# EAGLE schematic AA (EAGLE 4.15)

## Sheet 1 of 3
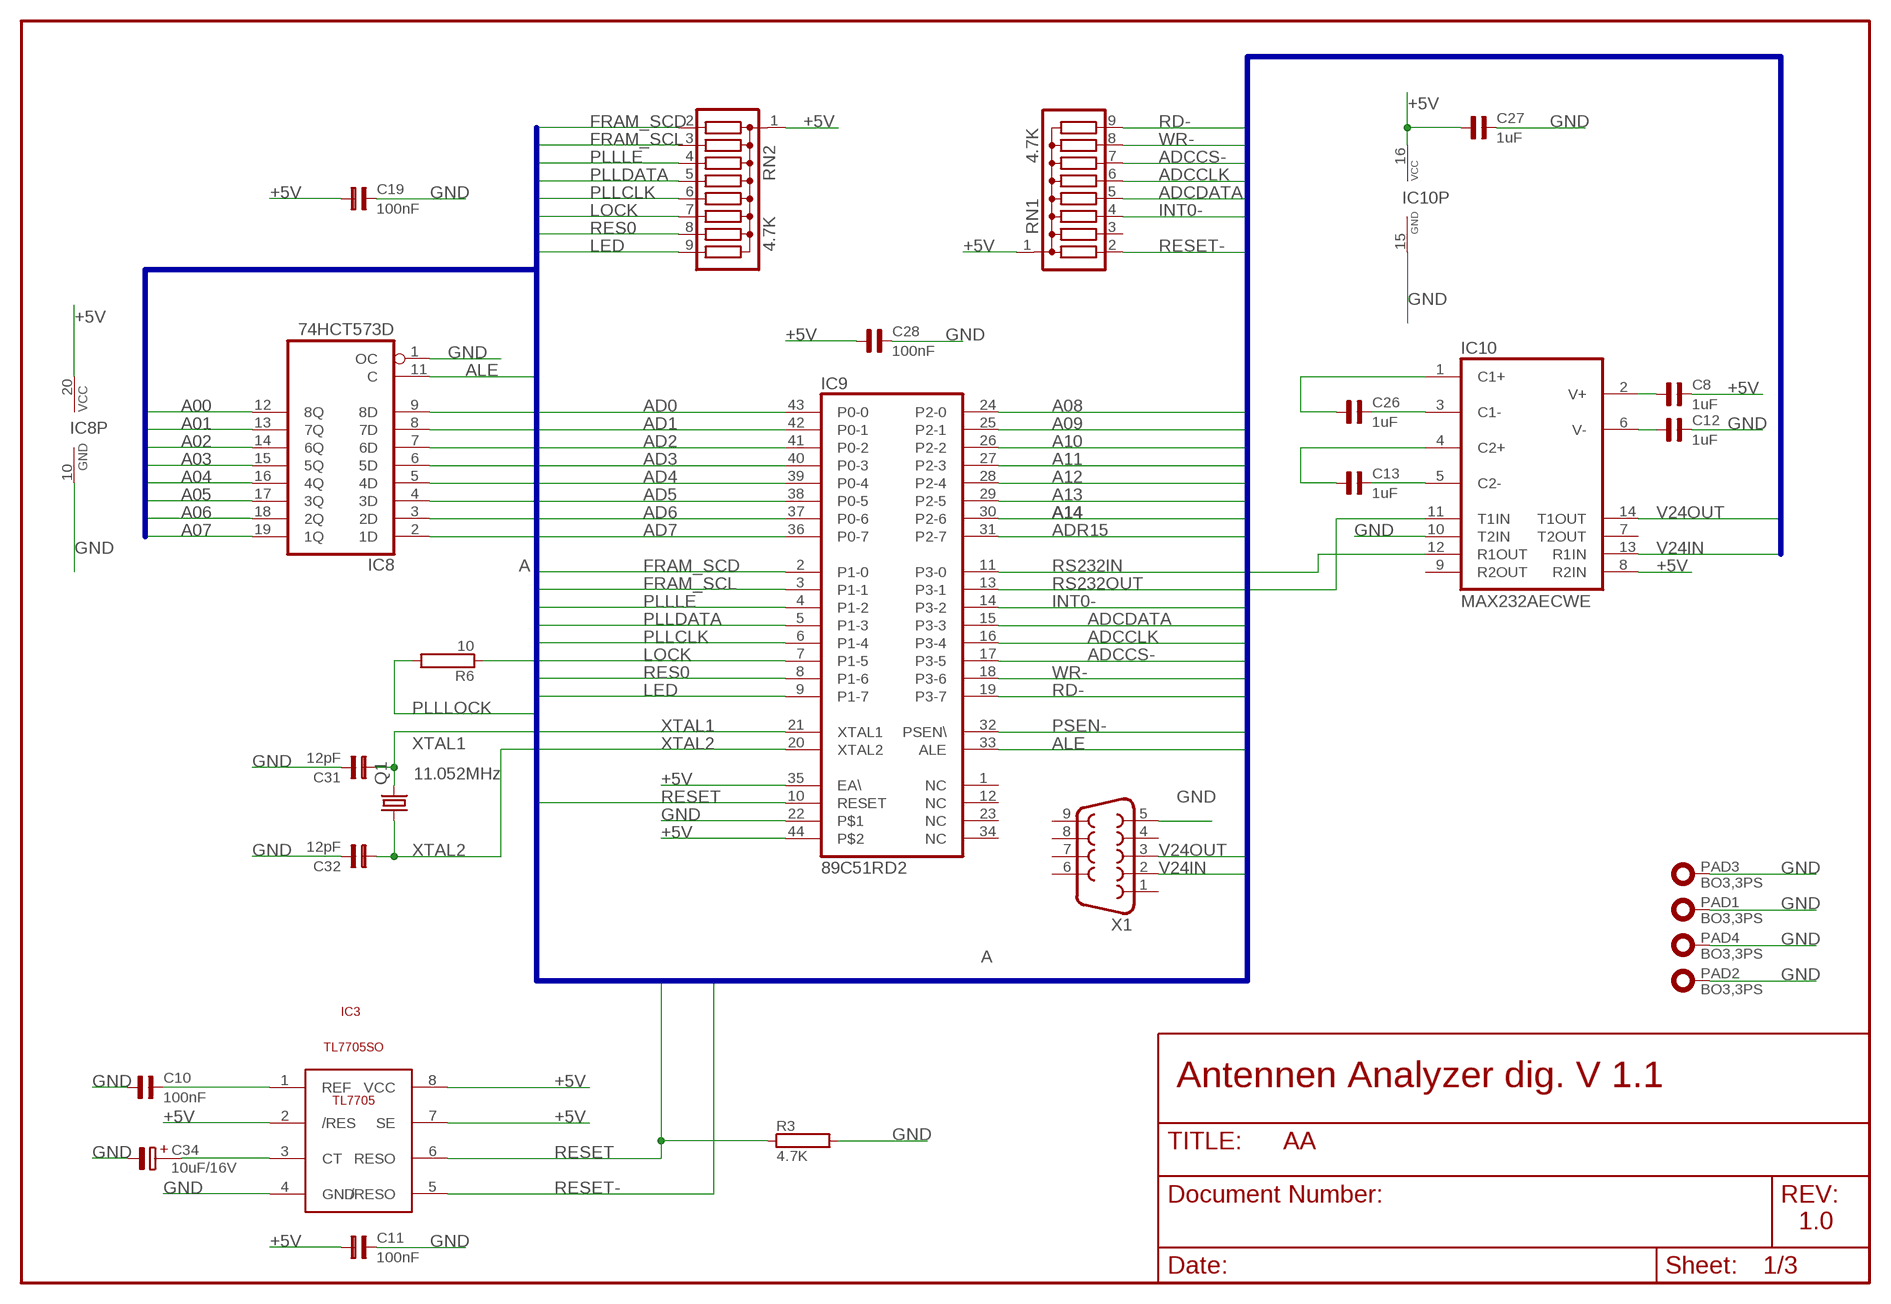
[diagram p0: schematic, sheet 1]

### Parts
C8  1uF  C-SMD1206  [C1206]
C10  100nF  C-SMD1206  [C1206]
C11  100nF  C-SMD1206  [C1206]
C12  1uF  C-SMD1206  [C1206]
C13  1uF  C-SMD1206  [C1206]
C19  100nF  C-SMD1206  [C1206]
C26  1uF  C-SMD1206  [C1206]
C27  1uF  C-SMD1206  [C1206]
C28  100nF  C-SMD1206  [C1206]
C31  12pF  C-SMD0805  [0805]
C32  12pF  C-SMD0805  [0805]
C34  10uF/16V  CT-SMD7243  [CT7243]
IC3  TL7705SO  [SOP-08]
IC8  74HCT573D  74AC573D  [SO20W]
IC9  89C51RD2  89C52PLCCS  [PLCC44SO]
IC10  MAX232AECWE  MAX232ECWE  [SO16L]
PAD1  BO3,3PS  [BO3,3-PS]
PAD2  BO3,3PS  [BO3,3-PS]
PAD3  BO3,3PS  [BO3,3-PS]
PAD4  BO3,3PS  [BO3,3-PS]
Q1  11.052MHz  HC18U-V  [HC18U-V]
R3  4.7K  R-SMD0805  [0805]
R6  10  R-SMD0805  [0805]
RN1  4.7K  G08R  [SIL9]
RN2  4.7K  G08R  [SIL9]
X1  F09H  [F09H]

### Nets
+5V: C8.2 C11.1 C19.1 C27.1 C28.1 IC3.2(/RES) IC3.7(SE) IC3.8(VCC) IC8.20(VCC) IC9.35(EA\) IC9.44 IC10.8(R2IN) IC10.16(VCC) RN1.1 RN2.1 ; also sheet 2,3
A00: IC8.12(8Q) ; also sheet 2
A01: IC8.13(7Q) ; also sheet 2
A02: IC8.14(6Q) ; also sheet 2
A03: IC8.15(5Q) ; also sheet 2
A04: IC8.16(4Q) ; also sheet 2
A05: IC8.17(3Q) ; also sheet 2
A06: IC8.18(2Q) ; also sheet 2
A07: IC8.19(1Q) ; also sheet 2
A08: IC9.24(P2-0) ; also sheet 2
A09: IC9.25(P2-1) ; also sheet 2
A10: IC9.26(P2-2) ; also sheet 2
A11: IC9.27(P2-3) ; also sheet 2
A12: IC9.28(P2-4) ; also sheet 2
A13: IC9.29(P2-5) ; also sheet 2
A14: IC9.30(P2-6) ; also sheet 2
AD0: IC8.9(8D) IC9.43(P0-0) ; also sheet 2
AD1: IC8.8(7D) IC9.42(P0-1) ; also sheet 2
AD2: IC8.7(6D) IC9.41(P0-2) ; also sheet 2
AD3: IC8.6(5D) IC9.40(P0-3) ; also sheet 2
AD4: IC8.5(4D) IC9.39(P0-4) ; also sheet 2
AD5: IC8.4(3D) IC9.38(P0-5) ; also sheet 2
AD6: IC8.3(2D) IC9.37(P0-6) ; also sheet 2
AD7: IC8.2(1D) IC9.36(P0-7) ; also sheet 2
ADCCLK: IC9.16(P3-4) RN1.6 ; also sheet 3
ADCCS-: IC9.17(P3-5) RN1.7 ; also sheet 3
ADCDATA: IC9.15(P3-3) RN1.5 ; also sheet 3
ADR15: IC9.31(P2-7) ; also sheet 2
ALE: IC8.11(C) IC9.33(ALE) ; also sheet 2
FRAM_SCD: IC9.2(P1-0) RN2.2 ; also sheet 2
FRAM_SCL: IC9.3(P1-1) RN2.3 ; also sheet 2
GND: C10.1 C11.2 C12.2 C19.2 C27.2 C28.2 C31.2 C32.2 C34.2(-) IC3.4(GND) IC8.1(OC) IC8.10(GND) IC9.22 IC10.10(T2IN) IC10.15(GND) PAD1.B3,3(P) PAD2.B3,3(P) PAD3.B3,3(P) PAD4.B3,3(P) R3.2 X1.5 ; also sheet 2,3
INT0-: IC9.14(P3-2) RN1.4 ; also sheet 2
LED: IC9.9(P1-7) RN2.9 ; also sheet 3
LOCK: IC9.7(P1-5) R6.1 RN2.7
N$1: C8.1 IC10.2(V+)
N$3: C34.1(+) IC3.3(CT)
N$4: C10.2 IC3.1(REF)
N$7: C13.2 IC10.5(C2-)
N$8: C13.1 IC10.4(C2+)
N$9: C26.2 IC10.3(C1-)
N$10: C26.1 IC10.1(C1+)
N$11: C12.1 IC10.6(V-)
PLLCLK: IC9.6(P1-4) RN2.6 ; also sheet 2
PLLDATA: IC9.5(P1-3) RN2.5 ; also sheet 2
PLLLE: IC9.4(P1-2) RN2.4 ; also sheet 2
PLLLOCK: R6.2 ; also sheet 3
PSEN-: IC9.32(PSEN\) ; also sheet 2
RD-: IC9.19(P3-7) RN1.9 ; also sheet 2
RES0: IC9.8(P1-6) RN2.8
RESET: IC3.6(RESO) IC9.10(RESET) R3.1
RESET-: IC3.5(/RESO) RN1.2 ; also sheet 2
RS232IN: IC9.11(P3-0) IC10.12(R1OUT)
RS232OUT: IC9.13(P3-1) IC10.11(T1IN)
V24IN: IC10.13(R1IN) X1.2
V24OUT: IC10.14(T1OUT) X1.3
WR-: IC9.18(P3-6) RN1.8 ; also sheet 2
XTAL1: C31.1 IC9.21(XTAL1) Q1.2
XTAL2: C32.1 IC9.20(XTAL2) Q1.1
Unconnected: IC9.1(NC) IC9.12(NC) IC9.23(NC) IC9.34(NC) IC10.7(T2OUT) IC10.9(R2OUT) RN1.3 X1.1 X1.4 X1.6 X1.7 X1.8 X1.9

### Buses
A

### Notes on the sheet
- Antennen Analyzer dig. V 1.1
- 1.0

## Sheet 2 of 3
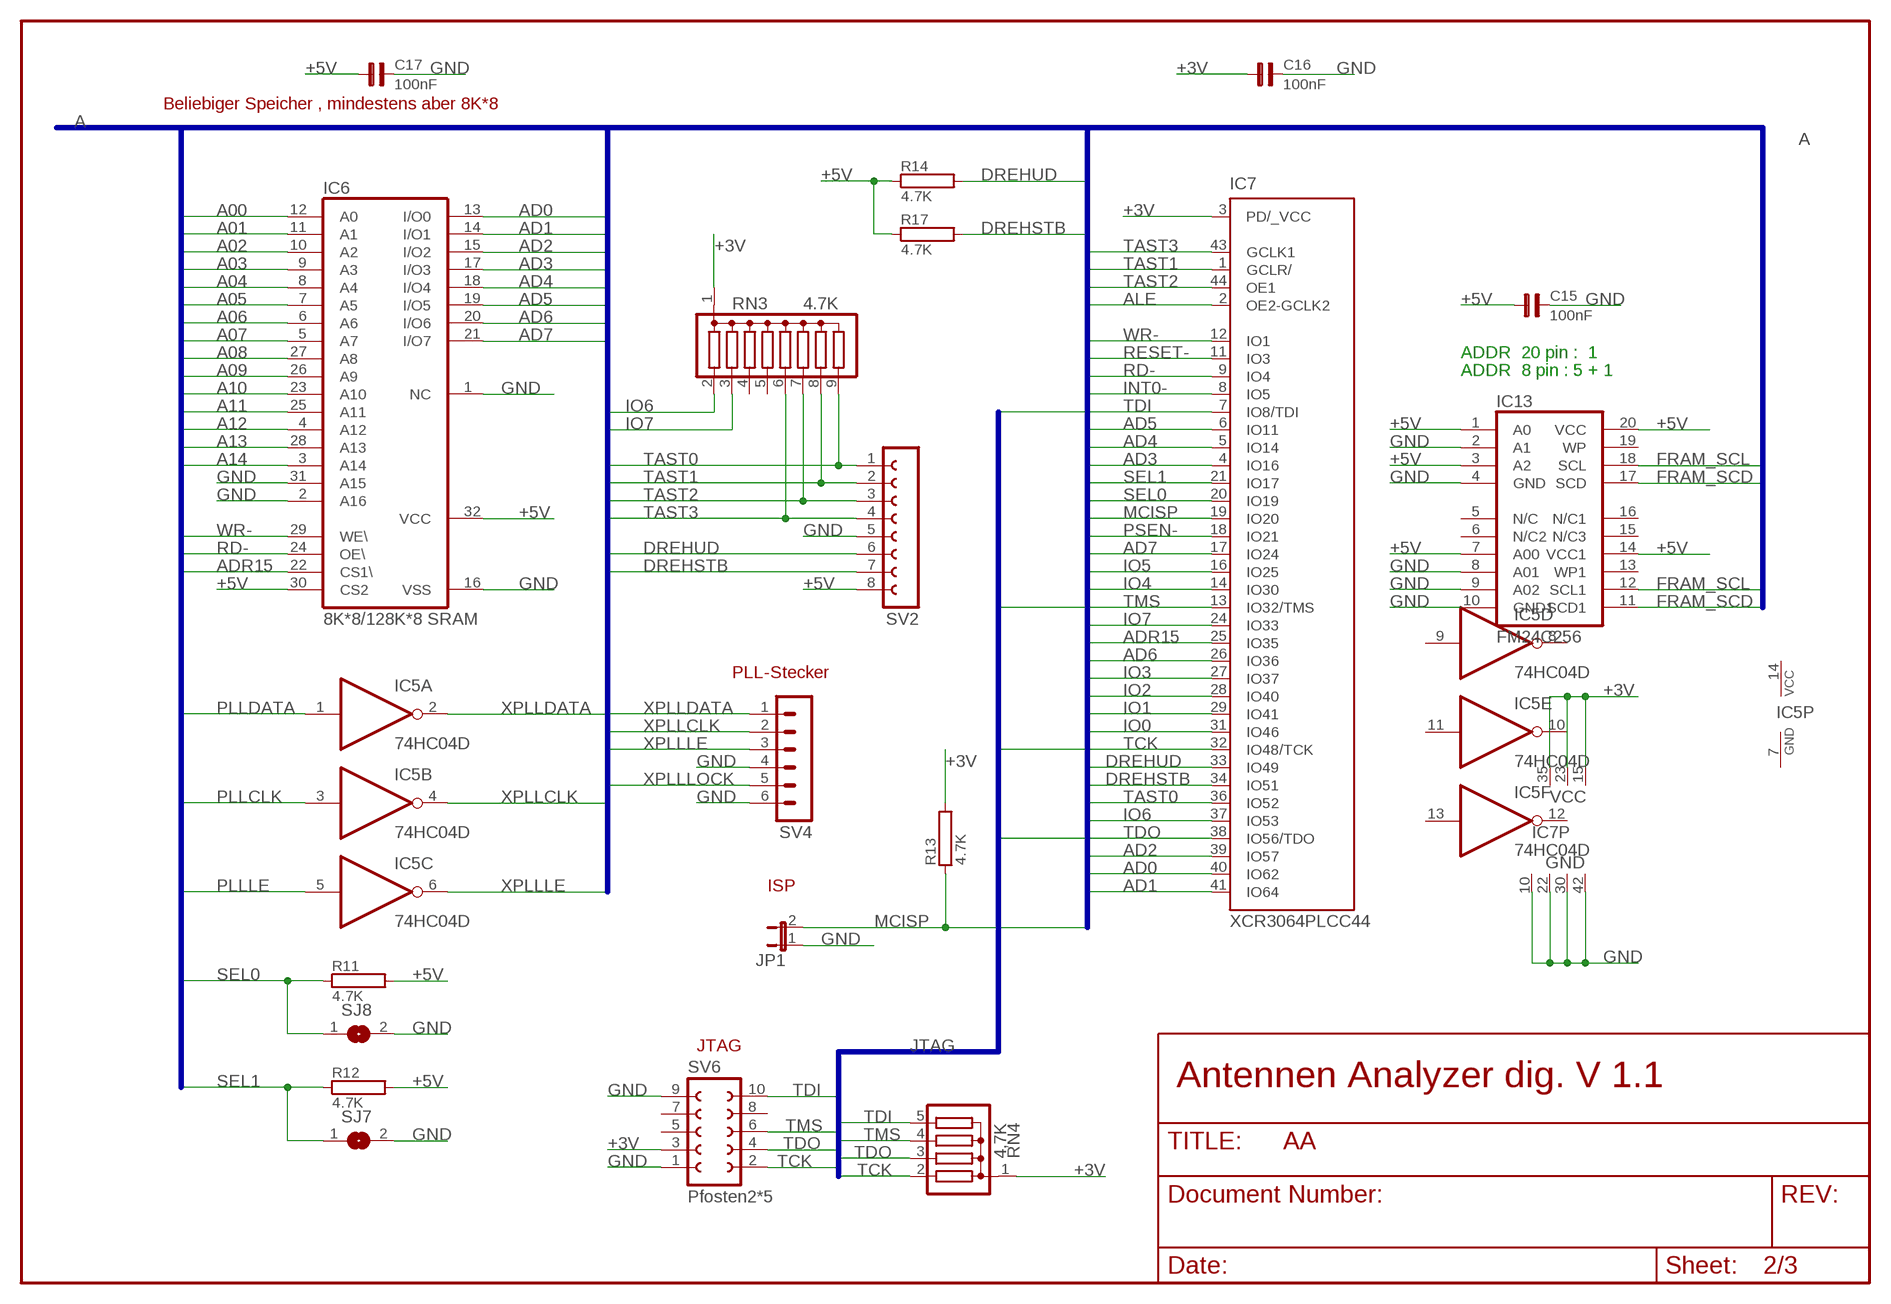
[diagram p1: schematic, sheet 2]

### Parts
C15  100nF  C-SMD1206  [C1206]
C16  100nF  C-SMD1206  [C1206]
C17  100nF  C-SMD1206  [C1206]
IC5  74HC04D  [SO14]
IC6  8K*8/128K*8 SRAM  628128P  [DIL32]
IC7  XCR3064PLCC44  EPM7064J44  [PLCC44]
IC13  FM24C256  [SO20W]
JP1  JP1E  [JP1]
R11  4.7K  R-SMD0805  [0805]
R12  4.7K  R-SMD0805  [0805]
R13  4.7K  R-SMD0805  [0805]
R14  4.7K  R-SMD0805  [0805]
R17  4.7K  R-SMD0805  [0805]
RN3  4.7K  G08R  [SIL9]
RN4  4,7K  G04R  [SIL5]
SJ7  SJ  [SJ]
SJ8  SJ  [SJ]
SV2  FE08-1  [FE08]
SV4  MA06-1  [MA06-1]
SV6  Pfosten2*5  FE05-2  [FE05-2]

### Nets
+3V: C16.1 IC7.3(PD/_VCC) IC7.15(VCC) IC7.23(VCC) IC7.35(VCC) R13.2 RN3.1 RN4.1 SV6.3 ; also sheet 3
+5V: C15.1 C17.1 IC6.30(CS2) IC6.32(VCC) IC13.1(A0) IC13.3(A2) IC13.7(A00) IC13.14(VCC1) IC13.20(VCC) R11.2 R12.2 R14.1 R17.1 SV2.8 ; also sheet 1,3
A00: IC6.12(A0) ; also sheet 1
A01: IC6.11(A1) ; also sheet 1
A02: IC6.10(A2) ; also sheet 1
A03: IC6.9(A3) ; also sheet 1
A04: IC6.8(A4) ; also sheet 1
A05: IC6.7(A5) ; also sheet 1
A06: IC6.6(A6) ; also sheet 1
A07: IC6.5(A7) ; also sheet 1
A08: IC6.27(A8) ; also sheet 1
A09: IC6.26(A9) ; also sheet 1
A10: IC6.23(A10) ; also sheet 1
A11: IC6.25(A11) ; also sheet 1
A12: IC6.4(A12) ; also sheet 1
A13: IC6.28(A13) ; also sheet 1
A14: IC6.3(A14) ; also sheet 1
AD0: IC6.13(I/O0) IC7.40(IO62) ; also sheet 1
AD1: IC6.14(I/O1) IC7.41(IO64) ; also sheet 1
AD2: IC6.15(I/O2) IC7.39(IO57) ; also sheet 1
AD3: IC6.17(I/O3) IC7.4(IO16) ; also sheet 1
AD4: IC6.18(I/O4) IC7.5(IO14) ; also sheet 1
AD5: IC6.19(I/O5) IC7.6(IO11) ; also sheet 1
AD6: IC6.20(I/O6) IC7.26(IO36) ; also sheet 1
AD7: IC6.21(I/O7) IC7.17(IO24) ; also sheet 1
ADR15: IC6.22(CS1\) IC7.25(IO35) ; also sheet 1
ALE: IC7.2(OE2-GCLK2) ; also sheet 1
DREHSTB: IC7.34(IO51) R17.2 SV2.7
DREHUD: IC7.33(IO49) R14.2 SV2.6
FRAM_SCD: IC13.11(SCD1) IC13.17(SCD) ; also sheet 1
FRAM_SCL: IC13.12(SCL1) IC13.18(SCL) ; also sheet 1
GND: C15.2 C16.2 C17.2 IC6.1(NC) IC6.2(A16) IC6.16(VSS) IC6.31(A15) IC7.10(GND) IC7.22(GND) IC7.30(GND) IC7.42(GND) IC13.2(A1) IC13.4(GND) IC13.8(A01) IC13.9(A02) IC13.10(GND1) JP1.1 SJ7.2 SJ8.2 SV2.5 SV4.4 SV4.6 SV6.1 SV6.9 ; also sheet 1,3
INT0-: IC7.8(IO5) ; also sheet 1
IO0: IC7.31(IO46) ; also sheet 3
IO1: IC7.29(IO41) ; also sheet 3
IO2: IC7.28(IO40) ; also sheet 3
IO3: IC7.27(IO37) ; also sheet 3
IO4: IC7.14(IO30) ; also sheet 3
IO5: IC7.16(IO25) ; also sheet 3
IO6: IC7.37(IO53) RN3.2 ; also sheet 3
IO7: IC7.24(IO33) RN3.3 ; also sheet 3
MCISP: IC7.19(IO20) JP1.2 R13.1
PLLCLK: IC5.3(B:I) ; also sheet 1
PLLDATA: IC5.1(A:I) ; also sheet 1
PLLLE: IC5.5(C:I) ; also sheet 1
PSEN-: IC7.18(IO21) ; also sheet 1
RD-: IC6.24(OE\) IC7.9(IO4) ; also sheet 1
RESET-: IC7.11(IO3) ; also sheet 1
SEL0: IC7.20(IO19) R11.1 SJ8.1
SEL1: IC7.21(IO17) R12.1 SJ7.1
TAST0: IC7.36(IO52) RN3.9 SV2.1
TAST1: IC7.1(GCLR/) RN3.8 SV2.2
TAST2: IC7.44(OE1) RN3.7 SV2.3
TAST3: IC7.43(GCLK1) RN3.6 SV2.4
TCK: IC7.32(IO48/TCK) RN4.2 SV6.2
TDI: IC7.7(IO8/TDI) RN4.5 SV6.10
TDO: IC7.38(IO56/TDO) RN4.3 SV6.4
TMS: IC7.13(IO32/TMS) RN4.4 SV6.6
WR-: IC6.29(WE\) IC7.12(IO1) ; also sheet 1
XPLLCLK: IC5.4(B:O) SV4.2
XPLLDATA: IC5.2(A:O) SV4.1
XPLLLE: IC5.6(C:O) SV4.3
XPLLLOCK: SV4.5 ; also sheet 3
Unconnected: IC13.5(N/C) IC13.6(N/C2) IC13.13(WP1) IC13.15(N/C3) IC13.16(N/C1) IC13.19(WP) RN3.4 RN3.5 SV6.5 SV6.7 SV6.8

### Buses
A
JTAG

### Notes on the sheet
- Beliebiger Speicher , mindestens aber 8K*8
- ADDR  20 pin :  1
- ADDR  8 pin : 5 + 1
- PLL-Stecker
- ISP
- JTAG
- Antennen Analyzer dig. V 1.1

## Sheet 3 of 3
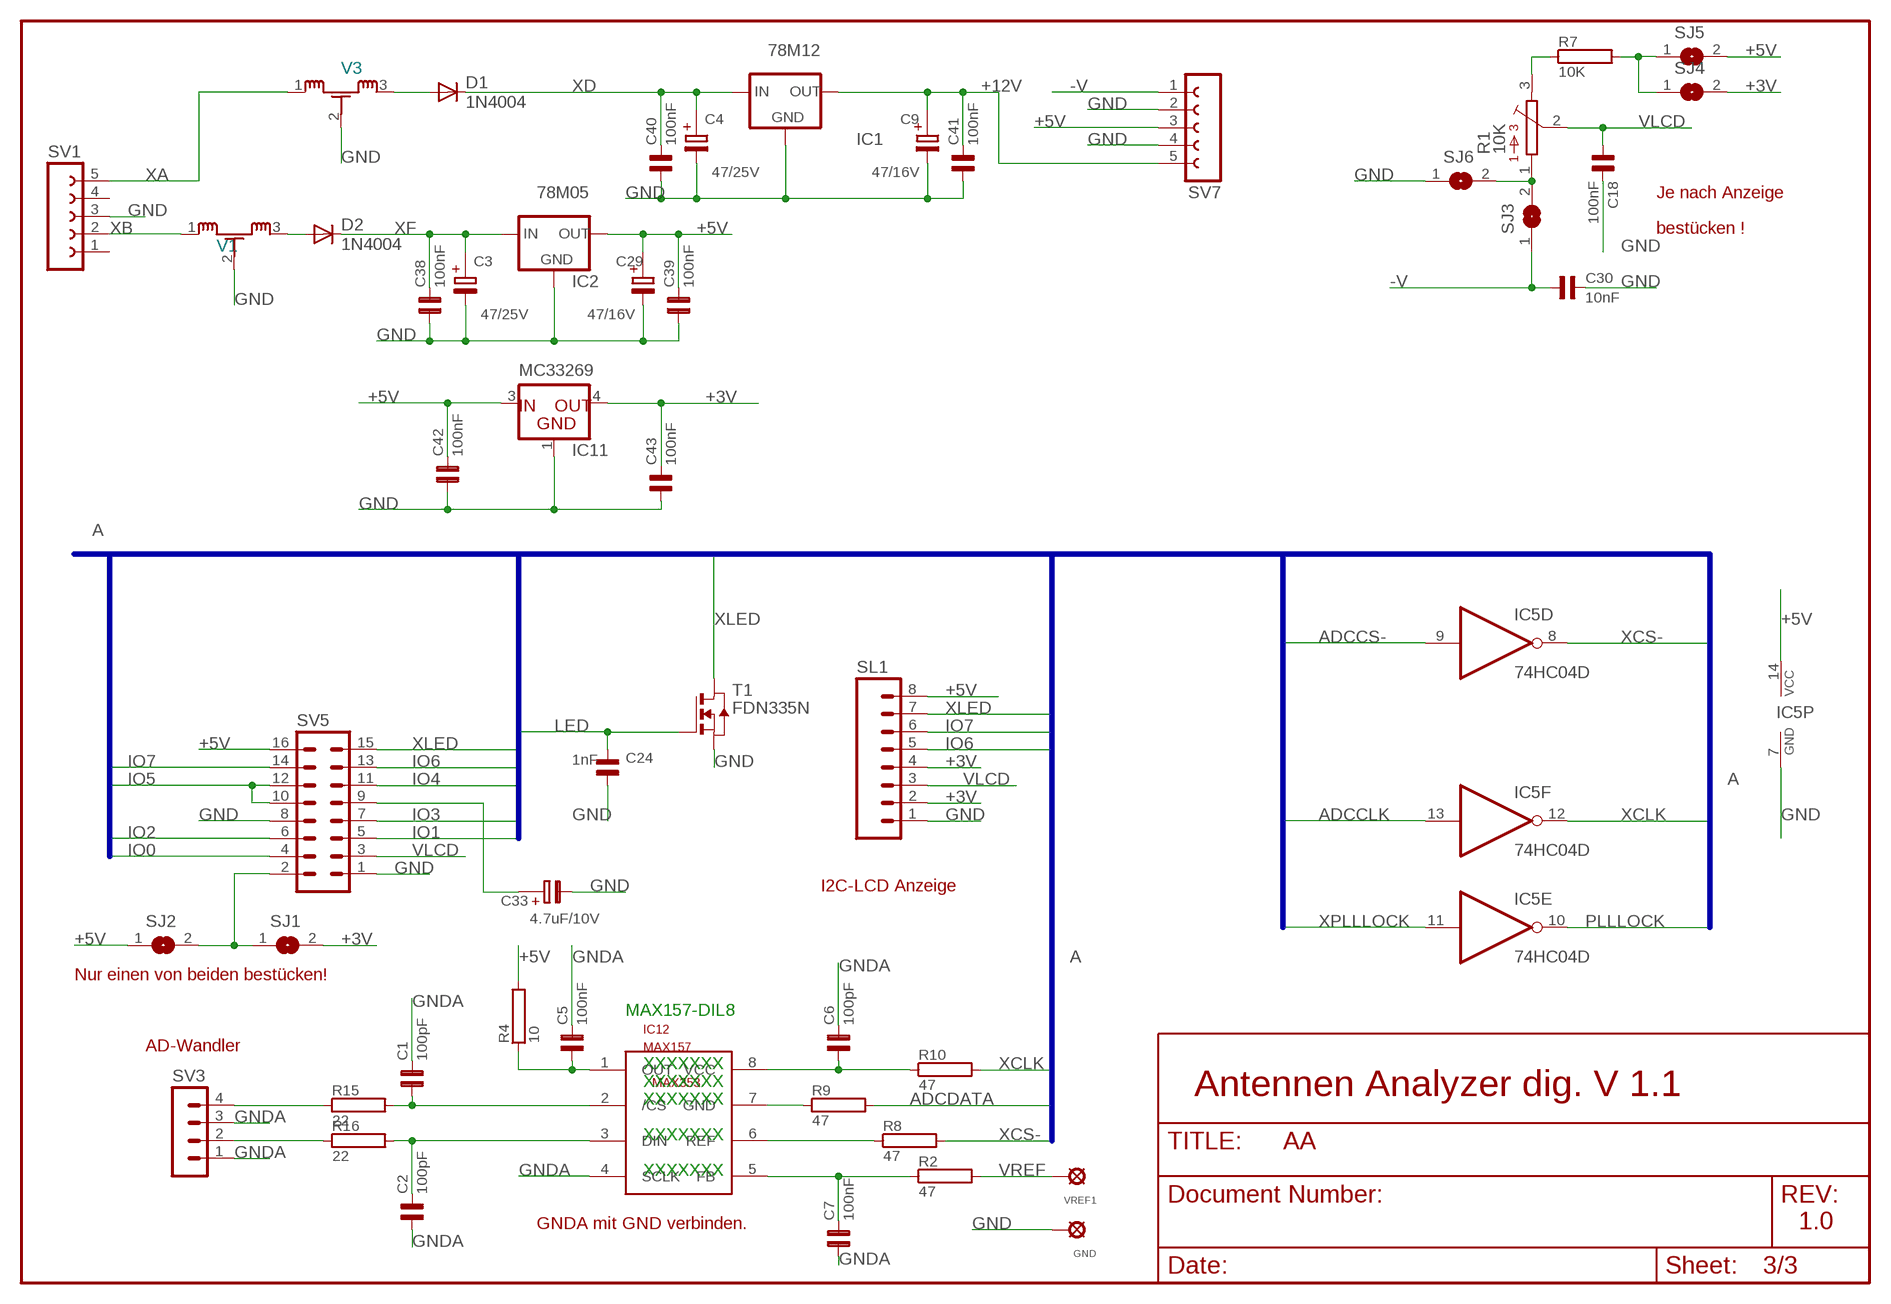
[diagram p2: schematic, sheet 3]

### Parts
C1  100pF  C-SMD0805  [0805]
C2  100pF  C-SMD0805  [0805]
C3  47/25V  TT5D9  [TT5D9]
C4  47/25V  TT5D9  [TT5D9]
C5  100nF  C-SMD1206  [C1206]
C6  100pF  C-SMD0805  [0805]
C7  100nF  C-SMD1206  [C1206]
C9  47/16V  TT5D9  [TT5D9]
C18  100nF  C-SMD1206  [C1206]
C24  1nF  C-SMD0805  [0805]
C29  47/16V  TT5D9  [TT5D9]
C30  10nF  C-SMD0805  [0805]
C33  4.7uF/10V  CT-SMD1210  [1210]
C38  100nF  C-SMD1206  [C1206]
C39  100nF  C-SMD1206  [C1206]
C40  100nF  C-SMD1206  [C1206]
C41  100nF  C-SMD1206  [C1206]
C42  100nF  C-SMD1206  [C1206]
C43  100nF  C-SMD1206  [C1206]
D1  1N4004  [DO41-10]
D2  1N4004  [DO41-10]
GND  LSP10  [LSP10]
IC1  78M12  78XXS  [78XXS]
IC2  78M05  78XXS  [78XXS]
IC11  MC33269  [DPAK]
IC12  MAX157  MAM353DIL  [DIL08]
R1  10K  ECP10P  [ECP10P]
R2  47  R-SMD0805  [0805]
R4  10  R-SMD0805  [0805]
R7  10K  R-SMD0805  [0805]
R8  47  R-SMD0805  [0805]
R9  47  R-SMD0805  [0805]
R10  47  R-SMD0805  [0805]
R15  22  R-SMD0805  [0805]
R16  22  R-SMD0805  [0805]
SJ1  SJ  [SJ]
SJ2  SJ  [SJ]
SJ3  SJ  [SJ]
SJ4  SJ  [SJ]
SJ5  SJ  [SJ]
SJ6  SJ  [SJ]
SL1  M08  [08P]
SV1  FE05-1  [FE05-1]
SV3  MA04-1  [MA04-1]
SV5  ML16  [ML16]
SV7  FE05-1  [FE05-1]
T1  FDN335N  [SOT-23]
V1  DSS306  [EMV1]
V2  DSS306  [EMV1]
VREF1  LSP10  [LSP10]

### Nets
+3V: C43.2 IC11.4(OUT) SJ1.2 SJ4.2 SL1.2 SL1.4 ; also sheet 2
+5V: C29.+ C39.2 C42.2 IC2.OUT IC5.14(P:VCC) IC11.3(IN) R4.2 SJ2.1 SJ5.2 SL1.8 SV5.16 SV7.3 ; also sheet 1,2
+12V: C9.+ C41.2 IC1.OUT SV7.5
-V: C30.1 SJ3.1 SV7.1
ADCCLK: IC5.13(F:I) ; also sheet 1
ADCCS-: IC5.9(D:I) ; also sheet 1
ADCDATA: R9.2 ; also sheet 1
GND: C3.- C4.- C9.- C18.2 C24.2 C29.- C30.2 C33.2(-) C38.1 C39.1 C40.1 C41.1 C42.1 C43.1 GND.MP IC1.GND IC2.GND IC5.7(P:GND) IC11.1(GND) SJ6.1 SL1.1 SV1.3 SV5.1 SV5.8 SV7.2 SV7.4 T1.1(S) V1.2 V2.2 ; also sheet 1,2
GNDA: C1.2 C2.1 C5.2 C6.2 C7.1 IC12.4(SCLK) SV3.1 SV3.3
IO0: SV5.4 ; also sheet 2
IO1: SV5.5 ; also sheet 2
IO2: SV5.6 ; also sheet 2
IO3: SV5.7 ; also sheet 2
IO4: SV5.11 ; also sheet 2
IO5: SV5.10 SV5.12 ; also sheet 2
IO6: SL1.5 SV5.13 ; also sheet 2
IO7: SL1.6 SV5.14 ; also sheet 2
LED: C24.1 T1.2(G) ; also sheet 1
N$5: D2.A V2.3
N$6: C5.1 IC12.1(OUT) R4.1
N$13: D1.A V1.3
N$17: R15.1 SV3.4
N$18: C1.1 IC12.2(/CS) R15.2
N$19: C7.2 IC12.5(FB) R2.1
N$20: C2.2 IC12.3(DIN) R16.2
N$21: R16.1 SV3.2
N$22: C6.1 IC12.8(VCC) R10.1
N$23: IC12.7(GND) R9.1
N$24: IC12.6(REF) R8.1
N$25: R1.3 R7.1
N$30: SJ1.1 SJ2.2 SV5.2
N$31: C33.1(+) SV5.9
N$32: R1.1 SJ3.2 SJ6.2
N$33: R7.2 SJ4.1 SJ5.1
PLLLOCK: IC5.10(E:O) ; also sheet 1
VLCD: C18.1 R1.2 SL1.3 SV5.3
VREF: R2.2 VREF1.MP
XA: SV1.5 V1.1
XB: SV1.2 V2.1
XCLK: IC5.12(F:O) R10.2
XCS-: IC5.8(D:O) R8.2
XD: C4.+ C40.2 D1.C IC1.IN
XF: C3.+ C38.2 D2.C IC2.IN
XLED: SL1.7 SV5.15 T1.3(D)
XPLLLOCK: IC5.11(E:I) ; also sheet 2
Unconnected: SV1.1 SV1.4

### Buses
A

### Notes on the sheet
- V3
- Je nach Anzeige
- bestücken !
- V1
- I2C-LCD Anzeige
- Nur einen von beiden bestücken!
- MAX157-DIL8
- AD-Wandler
- XXXXXXX
- XXXXXXX
- Antennen Analyzer dig. V 1.1
- XXXXXXX
- XXXXXXX
- XXXXXXX
- GNDA mit GND verbinden. | 1.0

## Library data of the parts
C1 C2 C6 C24 C30-C32 = ROB:C-SMD0805
C3 C4 C9 C29 = cap-tant:TT5D9
C5 C7 C8 C10-C13 C15-C19 C26-C28 C38-C43 = ROB:C-SMD1206
C33 = ROB:CT-SMD1210
C34 = ROB:CT-SMD7243
D1 D2 = diode:1N4004: DIODE
GND VREF1 = solpad:LSP10: SOLDER PAD
IC1 IC2 = v-reg:78XXS: VOLTAGE REGULATOR
IC3 = NEWLBR:TL7705SO
IC5 = 74xx-eu:74*04: Hex INVERTER
IC6 = memory-hitachi:628128P: MEMORY
IC7 = altera:EPM7064: EPM7064 MAX 7000 family
IC8 = 74xx-eu:74*573: 8-bit D latch BUS DRIVER
IC9 = ROB:89C52PLCCS
IC10 = maxim:MAX232ECWE: RS232 TRANSEIVER
IC11 = ROB:MC33269
IC12 = ROB:MAM353DIL
IC13 = ROB:FM24C256: FM24C256 32K Serial FRAM
JP1 = jumper:JP1E: JUMPER
PAD1-PAD4 = HOLES:BO3,3PS
Q1 = crystal:HC18U-V: CRYSTAL
R1 = pot:ECP10P: POTENTIOMETER
R2-R4 R6-R17 = ROB:R-SMD0805
RN1-RN3 = resistor-sil:G08R: SIL RESISTOR
RN4 = resistor-sil:G04R: SIL RESISTOR
SJ1-SJ8 = jumper:SJ: SMD solder JUMPER
SL1 = con-amp-quick:M08: AMP QUICK CONNECTOR
SV1 SV7 = con-lsta:FE05-1: FEMALE HEADER
SV2 = con-lsta:FE08-1: FEMALE HEADER
SV3 = con-lstb:MA04-1: PIN HEADER
SV4 = con-lstb:MA06-1: PIN HEADER
SV5 = CON-ML:ML16: HARTING
SV6 = con-lsta:FE05-2: FEMALE HEADER
T1 = ROB:FDN335N: N-Fet FDN335N SOT23
V1 V2 = ROB:DSS306
X1 = con-subd:F09: SUB-D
